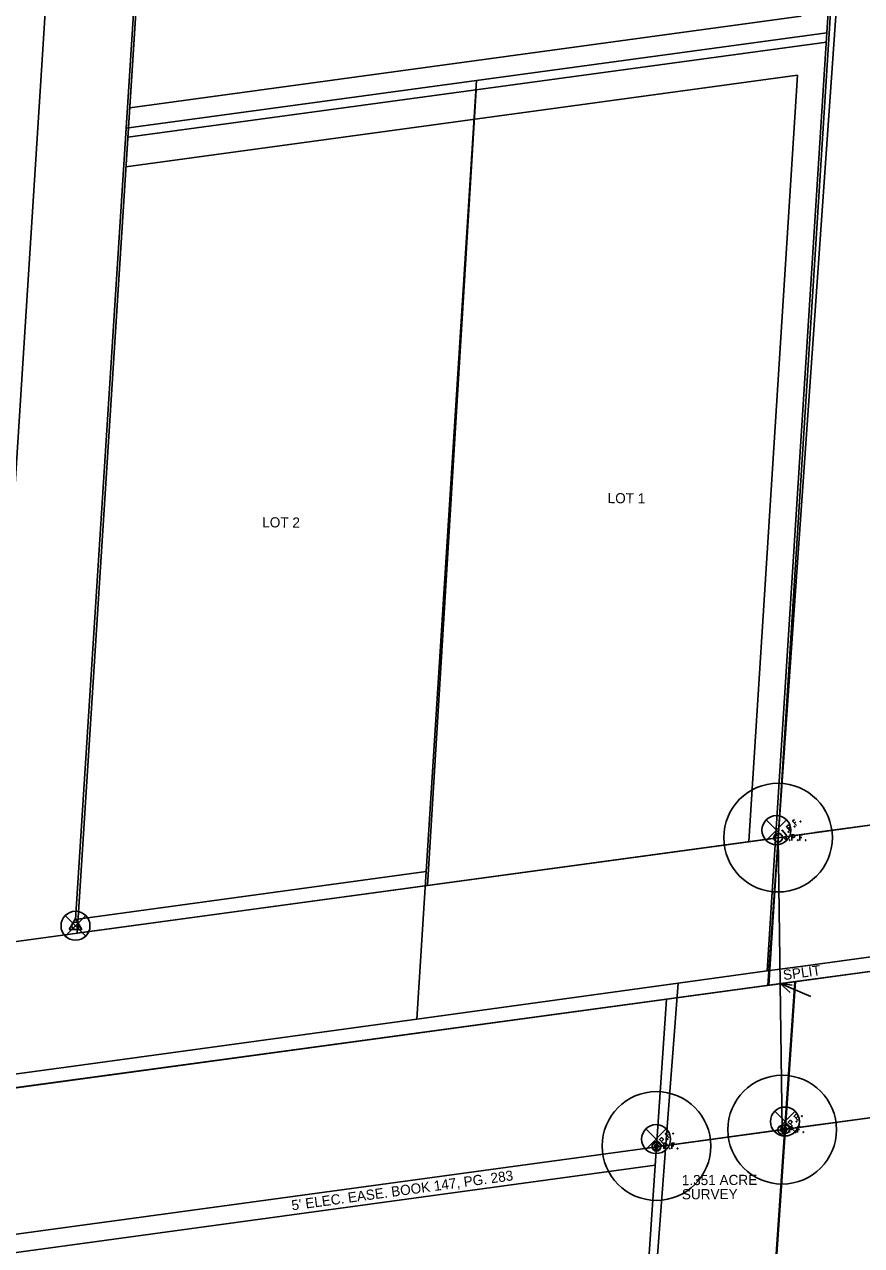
# Model space of a CAD drawing. Extents: x 1532954 to 1577849, y 698998 to 706606.
# Drawn here: x 1573832.2 to 1574063.3, y 703101.1 to 703438.2 of the extents above; entities that cross this region are included whole.
import ezdxf

# ---------------------------------------------------------------- set-up
doc = ezdxf.new("R2010")
doc.units = 0
for name, color, linetype in [('Default', 7, 'Continuous'), ('DV_X_Lot_Line', 7, 'Continuous'), ('DV_X_Property_Line', 7, 'Continuous'), ('RW_X_CL', 7, 'Continuous'), ('RW_X_Esmt_SH', 7, 'Continuous'), ('RW_X_Esmt_U', 7, 'Continuous'), ('RW_X_Fee_RW', 7, 'Continuous'), ('RW_X_Text', 7, 'Continuous'), ('SC_Scratch1', 7, 'Continuous'), ('SC_Scratch10', 7, 'Continuous'), ('SC_Scratch2', 7, 'Continuous'), ('SC_Scratch3', 7, 'Continuous'), ('SC_Scratch4', 7, 'Continuous'), ('SC_Scratch9', 7, 'Continuous'), ('SV_Control_Point', 7, 'Continuous'), ('SV_X_Mon_Cells_Found', 7, 'Continuous')]:
    doc.layers.add(name, color=color, linetype=linetype)

msp = doc.modelspace()

# ---------------------------------------------------------------- linework, layer by layer
at = {"layer": 'Default'}
for p, q in [((1574036.95, 703218.63), (1574042.61, 703212.98)), ((1574036.95, 703212.98), (1574042.61, 703218.63)), ((1574039.78, 703215.8), (1574039.78, 703215.8)), ((1573843.48, 703192.24), (1573849.14, 703186.58)), ((1573843.48, 703186.58), (1573849.14, 703192.24)), ((1573846.31, 703189.41), (1573846.31, 703189.41)), ((1574039.31, 703138.22), (1574044.97, 703132.56)), ((1574039.31, 703132.56), (1574044.97, 703138.22)), ((1574042.14, 703135.39), (1574042.14, 703135.39)), ((1574003.74, 703133.36), (1574009.4, 703127.7)), ((1574003.74, 703127.7), (1574009.4, 703133.36)), ((1574006.57, 703130.53), (1574006.57, 703130.53))]:
    msp.add_line(p, q, dxfattribs=at)
for centre in [(1574039.78, 703215.8), (1573846.31, 703189.41), (1574042.14, 703135.39), (1574006.57, 703130.53)]:
    msp.add_circle(centre, 4, dxfattribs=at)
at = {"layer": 'DV_X_Lot_Line'}
for p, q in [((1573943.52, 703200.54), (1573956.87, 703420.13)), ((1574044.83, 703173.97), (1574028.81, 702938.8))]:
    msp.add_line(p, q, dxfattribs=at)
at = {"layer": 'DV_X_Property_Line'}
for p, q in [((1574037.66, 703173), (1574084.63, 703911.12)), ((1573860.76, 703407.03), (1574053.61, 703433.31)), ((1573991.25, 702903.04), (1574009.46, 703169.15))]:
    msp.add_line(p, q, dxfattribs=at)
at = {"layer": 'RW_X_CL'}
msp.add_line((1573818.91, 703143.18), (1573849.35, 703621.38), dxfattribs=at)
at = {"layer": 'RW_X_Esmt_SH'}
for p, q in [((1574050.43, 703215.11), (1574859.76, 703325.41)), ((1571959, 702849.32), (1574870.56, 703246.15))]:
    msp.add_line(p, q, dxfattribs=at)
at = {"layer": 'RW_X_Esmt_U'}
for p, q in [((1573861.27, 703415.17), (1574046.66, 703440.44)), ((1573860.24, 703398.88), (1574045.63, 703424.15)), ((1574032.16, 703212.62), (1574045.63, 703424.15)), ((1574006.32, 703123.31), (1574006.67, 703128.4)), ((1573740.72, 703087.11), (1574006.32, 703123.31))]:
    msp.add_line(p, q, dxfattribs=at)
at = {"layer": 'RW_X_Fee_RW'}
for p, q in [((1573846.78, 703187.35), (1573874.62, 703624.83)), ((1573846.78, 703187.35), (1574040.25, 703213.72)), ((1574037.66, 703173), (1574040.25, 703213.72))]:
    msp.add_line(p, q, dxfattribs=at)
at = {"layer": 'SC_Scratch1'}
for points in [[(1574623.21, 704615.75), (1574580.13, 703940.99), (1574479.08, 703927.65), (1574283.38, 703901.81), (1574176.78, 703887.73), (1574134.84, 703230.69), (1574132.24, 703189.96), (1574047.81, 703178.38), (1574037.25, 703176.93), (1574039.84, 703217.66), (1574053.75, 703435.89), (1574059.56, 703527.11), (1574066.62, 703637.88), (1574073.68, 703748.66), (1574080.74, 703859.43), (1574081.75, 703875.18), (1574087.8, 703970.21), (1574094.86, 704080.98), (1574101.92, 704191.76)], [(1573381.77, 703087.06), (1573407.03, 703090.53), (1573503.76, 703103.79), (1573600.48, 703117.05), (1573696.98, 703130.28), (1573793.21, 703143.47), (1573818.48, 703146.94), (1573843.76, 703150.4), (1573940.5, 703163.67), (1574012.63, 703173.56), (1574009.55, 703132.76), (1573992.57, 702907.55), (1573992.57, 702907.55), (1574153.57, 702895.41), (1574152.55, 702881.84), (1574277.72, 702872.4), (1574506.31, 702855.16), (1574480.3, 702510.33), (1574373.41, 701092.97)]]:
    msp.add_lwpolyline(points, dxfattribs=at)
for points in [[(1574059.56, 703527.11), (1574059.56, 703527.11), (1574053.75, 703435.89), (1573957.01, 703422.72), (1573860.27, 703409.54), (1573868.54, 703539.28)], [(1574039.84, 703217.66), (1574037.25, 703176.93), (1574012.63, 703173.56), (1573940.5, 703163.67), (1573943.1, 703204.4), (1573957.01, 703422.72), (1574053.75, 703435.89)], [(1573943.1, 703204.4), (1573846.35, 703191.13), (1573860.27, 703409.54), (1573957.01, 703422.72)], [(1574173.16, 703155.19), (1574157.49, 702947.32), (1574153.57, 702895.41), (1573992.57, 702907.55), (1573992.57, 702907.55), (1574009.55, 703132.76), (1574012.63, 703173.56), (1574037.25, 703176.93), (1574047.81, 703178.38), (1574132.24, 703189.96), (1574176.24, 703195.99)]]:
    msp.add_lwpolyline(points, close=True, dxfattribs=at)
at = {"layer": 'SC_Scratch10'}
for p, q in [((1571190.11, 702825.26), (1574958.12, 703338.82)), ((1571190.11, 702825.26), (1574958.12, 703338.82)), ((1571190.11, 702825.26), (1574958.12, 703338.82)), ((1571195.51, 702785.63), (1574963.52, 703299.19)), ((1571200.91, 702745.99), (1574968.92, 703259.55))]:
    msp.add_line(p, q, dxfattribs=at)
at = {"layer": 'SC_Scratch2'}
for p, q in [((1574175.23, 705334.64), (1574037.66, 703173)), ((1573874.62, 703624.83), (1573846.78, 703187.35)), ((1573849.35, 703621.38), (1573818.91, 703143.18)), ((1574046.66, 703440.44), (1573861.27, 703415.17)), ((1574053.61, 703433.31), (1573860.76, 703407.03)), ((1574045.63, 703424.15), (1573860.24, 703398.88)), ((1574045.63, 703424.15), (1574032.16, 703212.62)), ((1573943.52, 703200.54), (1573956.87, 703420.13)), ((1574040.25, 703213.72), (1573846.78, 703187.35)), ((1574037.66, 703173), (1573356.99, 703080.23))]:
    msp.add_line(p, q, dxfattribs=at)
at = {"layer": 'SC_Scratch3'}
for p, q in [((1574037.38, 703172.96), (1574089.44, 703911.99)), ((1574832.97, 703321.42), (1574040.25, 703213.72)), ((1574830.1, 703280.66), (1574037.38, 703172.96)), ((1574533, 703240.3), (1572963.42, 703027.05)), ((1574172.81, 703191.36), (1574045.04, 703174)), ((1574045.04, 703174), (1574009.47, 703169.17)), ((1574045.04, 703174), (1574028.74, 702936.66)), ((1574009.47, 703169.17), (1573991.19, 702903.04)), ((1574042.24, 703133.25), (1574006.67, 703128.42))]:
    msp.add_line(p, q, dxfattribs=at)
for points in [[(1574044.81, 703218.78), (1574044.24, 703218.28), (1574045.29, 703217.07)], [(1574044.75, 703217.69), (1574045.16, 703218.05)], [(1574046.31, 703218.25), (1574046.35, 703218.29), (1574046.4, 703218.29), (1574046.45, 703218.28), (1574046.5, 703218.23), (1574046.5, 703218.17), (1574046.5, 703218.13), (1574046.45, 703218.09), (1574046.41, 703218.09), (1574046.36, 703218.1), (1574046.31, 703218.15), (1574046.31, 703218.21), (1574046.31, 703218.25)], [(1574041.24, 703215.65), (1574041.5, 703215.88)], [(1574042.43, 703214.56), (1574041.37, 703215.76)], [(1574042.29, 703214.44), (1574042.56, 703214.68)], [(1574043.6, 703215.59), (1574042.55, 703216.8), (1574042.95, 703217.14), (1574043, 703217.17), (1574043.07, 703217.2), (1574043.11, 703217.21), (1574043.15, 703217.21), (1574043.23, 703217.19), (1574043.29, 703217.16), (1574043.38, 703217.1), (1574043.48, 703216.99), (1574043.5, 703216.94), (1574043.54, 703216.87), (1574043.56, 703216.78), (1574043.55, 703216.72), (1574043.54, 703216.68), (1574043.52, 703216.62), (1574043.46, 703216.56), (1574043.06, 703216.21)], [(1574043.01, 703215.35), (1574043.05, 703215.39), (1574043.09, 703215.39), (1574043.15, 703215.38), (1574043.19, 703215.33), (1574043.2, 703215.27), (1574043.19, 703215.23), (1574043.15, 703215.19), (1574043.11, 703215.19), (1574043.05, 703215.21), (1574043.01, 703215.25), (1574043, 703215.31), (1574043.01, 703215.35)], [(1574044.7, 703216.84), (1574044.74, 703216.87), (1574044.78, 703216.88), (1574044.84, 703216.86), (1574044.88, 703216.81), (1574044.89, 703216.75), (1574044.88, 703216.71), (1574044.84, 703216.67), (1574044.8, 703216.67), (1574044.74, 703216.69), (1574044.7, 703216.74), (1574044.69, 703216.8), (1574044.7, 703216.84)], [(1574008.64, 703129.27), (1574007.51, 703130.4), (1574007.88, 703130.78), (1574007.93, 703130.81), (1574008, 703130.84), (1574008.04, 703130.85), (1574008.08, 703130.86), (1574008.16, 703130.84), (1574008.23, 703130.82), (1574008.31, 703130.77), (1574008.42, 703130.66), (1574008.45, 703130.62), (1574008.49, 703130.55), (1574008.52, 703130.45), (1574008.51, 703130.4), (1574008.51, 703130.36), (1574008.49, 703130.3), (1574008.43, 703130.23), (1574008.06, 703129.85)], [(1574009.63, 703132.54), (1574009.09, 703132), (1574010.23, 703130.87)], [(1574009.65, 703130.59), (1574009.69, 703130.63), (1574009.73, 703130.64), (1574009.79, 703130.62), (1574009.83, 703130.58), (1574009.84, 703130.52), (1574009.84, 703130.48), (1574009.8, 703130.44), (1574009.76, 703130.44), (1574009.7, 703130.45), (1574009.66, 703130.49), (1574009.64, 703130.55), (1574009.65, 703130.59)], [(1574009.65, 703131.45), (1574010.03, 703131.83)], [(1574011.16, 703132.12), (1574011.2, 703132.16), (1574011.24, 703132.16), (1574011.3, 703132.15), (1574011.35, 703132.11), (1574011.36, 703132.05), (1574011.35, 703132.01), (1574011.31, 703131.97), (1574011.27, 703131.96), (1574011.21, 703131.97), (1574011.17, 703132.02), (1574011.16, 703132.08), (1574011.16, 703132.12)]]:
    msp.add_lwpolyline(points, dxfattribs=at)
for centre, radius in [((1574040.25, 703213.72), 1.2), ((1574006.67, 703128.42), 1.2), ((1574006.67, 703128.42), 0.495)]:
    msp.add_circle(centre, radius, dxfattribs=at)
at = {"layer": 'SC_Scratch4'}
for p, q in [((1574045.04, 703174.01), (1574172.81, 703191.37)), ((1574028.74, 702936.67), (1574045.04, 703174.01)), ((1574042.24, 703133.26), (1574170.01, 703150.62))]:
    msp.add_line(p, q, dxfattribs=at)
for points in [[(1574045.2, 703137.38), (1574044.66, 703136.84), (1574045.8, 703135.71)], [(1574046.73, 703136.96), (1574046.77, 703137), (1574046.81, 703137), (1574046.87, 703136.99), (1574046.92, 703136.94), (1574046.93, 703136.89), (1574046.92, 703136.84), (1574046.89, 703136.81), (1574046.84, 703136.8), (1574046.79, 703136.81), (1574046.74, 703136.86), (1574046.73, 703136.92), (1574046.73, 703136.96)], [(1574044.22, 703134.11), (1574043.08, 703135.24), (1574043.45, 703135.62), (1574043.5, 703135.65), (1574043.57, 703135.68), (1574043.61, 703135.69), (1574043.65, 703135.69), (1574043.73, 703135.68), (1574043.8, 703135.66), (1574043.89, 703135.61), (1574043.99, 703135.5), (1574044.02, 703135.46), (1574044.06, 703135.39), (1574044.09, 703135.29), (1574044.09, 703135.24), (1574044.08, 703135.19), (1574044.06, 703135.14), (1574044.01, 703135.07), (1574043.63, 703134.69)], [(1574045.22, 703135.43), (1574045.26, 703135.47), (1574045.3, 703135.48), (1574045.36, 703135.46), (1574045.4, 703135.42), (1574045.42, 703135.36), (1574045.41, 703135.32), (1574045.37, 703135.28), (1574045.33, 703135.27), (1574045.27, 703135.29), (1574045.23, 703135.33), (1574045.21, 703135.39), (1574045.22, 703135.43)], [(1574045.22, 703136.29), (1574045.6, 703136.67)]]:
    msp.add_lwpolyline(points, dxfattribs=at)
for radius in [1.2, 0.495]:
    msp.add_circle((1574042.24, 703133.26), radius, dxfattribs=at)
at = {"layer": 'SC_Scratch9'}
for p, q in [((1574040.25, 703213.73), (1574041.39, 703133.13)), ((1574040.82, 703173.43), (1574049.3, 703169.89)), ((1574040.82, 703173.43), (1574043.61, 703171.02)), ((1574040.82, 703173.43), (1574044.14, 703173.01))]:
    msp.add_line(p, q, dxfattribs=at)
for centre in [(1574040.25, 703213.73), (1574041.39, 703133.13), (1574006.68, 703128.63)]:
    msp.add_circle(centre, 15, dxfattribs=at)
at = {"layer": 'SV_Control_Point'}
msp.add_line((1573846.31, 703189.41), (1573846.31, 703189.41), dxfattribs=at)
msp.add_lwpolyline([(1573844.57, 703188.41), (1573846.31, 703191.41), (1573848.04, 703188.41)], close=True, dxfattribs=at)
msp.add_circle((1573846.31, 703189.41), 1, dxfattribs=at)
at = {"layer": 'SV_X_Mon_Cells_Found'}
msp.add_line((1574040.25, 703213.85), (1574040.25, 703212.96), dxfattribs=at)
for points in [[(1574042.28, 703214.53), (1574042.63, 703214.53)], [(1574042.46, 703212.93), (1574042.46, 703214.53)], [(1574044.02, 703212.93), (1574044.02, 703214.53), (1574044.55, 703214.53), (1574044.61, 703214.52), (1574044.68, 703214.49), (1574044.72, 703214.47), (1574044.75, 703214.44), (1574044.79, 703214.38), (1574044.83, 703214.31), (1574044.85, 703214.21), (1574044.85, 703214.06), (1574044.84, 703214.01), (1574044.82, 703213.94), (1574044.77, 703213.85), (1574044.73, 703213.81), (1574044.7, 703213.79), (1574044.64, 703213.76), (1574044.55, 703213.75), (1574044.02, 703213.75)], [(1574047.03, 703214.53), (1574046.27, 703214.53), (1574046.27, 703212.93)], [(1574042.28, 703212.93), (1574042.63, 703212.93)], [(1574043.42, 703213.14), (1574043.47, 703213.14), (1574043.51, 703213.12), (1574043.54, 703213.07), (1574043.54, 703213), (1574043.51, 703212.95), (1574043.47, 703212.93), (1574043.42, 703212.93), (1574043.38, 703212.95), (1574043.35, 703213), (1574043.35, 703213.07), (1574043.38, 703213.12), (1574043.42, 703213.14)], [(1574045.67, 703213.14), (1574045.72, 703213.14), (1574045.75, 703213.12), (1574045.79, 703213.07), (1574045.79, 703213), (1574045.75, 703212.95), (1574045.72, 703212.93), (1574045.67, 703212.93), (1574045.63, 703212.95), (1574045.6, 703213), (1574045.6, 703213.07), (1574045.63, 703213.12), (1574045.67, 703213.14)], [(1574046.27, 703213.75), (1574046.81, 703213.75)], [(1574047.82, 703213.14), (1574047.87, 703213.14), (1574047.9, 703213.12), (1574047.94, 703213.07), (1574047.94, 703213), (1574047.9, 703212.95), (1574047.87, 703212.93), (1574047.82, 703212.93), (1574047.78, 703212.95), (1574047.75, 703213), (1574047.75, 703213.07), (1574047.78, 703213.12), (1574047.82, 703213.14)], [(1574043.38, 703132.33), (1574043.38, 703133.93), (1574043.91, 703133.93), (1574043.97, 703133.91), (1574044.05, 703133.89), (1574044.08, 703133.86), (1574044.11, 703133.84), (1574044.16, 703133.77), (1574044.19, 703133.71), (1574044.21, 703133.61), (1574044.21, 703133.46), (1574044.2, 703133.41), (1574044.18, 703133.33), (1574044.13, 703133.25), (1574044.09, 703133.21), (1574044.06, 703133.18), (1574044, 703133.16), (1574043.91, 703133.14), (1574043.38, 703133.14)], [(1574046.39, 703133.93), (1574045.63, 703133.93), (1574045.63, 703132.33)], [(1574045.03, 703132.54), (1574045.08, 703132.54), (1574045.12, 703132.51), (1574045.15, 703132.46), (1574045.15, 703132.4), (1574045.12, 703132.35), (1574045.08, 703132.33), (1574045.03, 703132.33), (1574044.99, 703132.35), (1574044.96, 703132.4), (1574044.96, 703132.46), (1574044.99, 703132.51), (1574045.03, 703132.54)], [(1574045.63, 703133.14), (1574046.17, 703133.14)], [(1574047.18, 703132.54), (1574047.23, 703132.54), (1574047.26, 703132.51), (1574047.3, 703132.46), (1574047.3, 703132.4), (1574047.26, 703132.35), (1574047.23, 703132.33), (1574047.18, 703132.33), (1574047.14, 703132.35), (1574047.11, 703132.4), (1574047.11, 703132.46), (1574047.14, 703132.51), (1574047.18, 703132.54)], [(1574008.68, 703127.83), (1574008.68, 703129.43), (1574009.21, 703129.43), (1574009.27, 703129.42), (1574009.34, 703129.39), (1574009.38, 703129.37), (1574009.41, 703129.34), (1574009.45, 703129.28), (1574009.49, 703129.21), (1574009.51, 703129.11), (1574009.51, 703128.96), (1574009.5, 703128.91), (1574009.47, 703128.84), (1574009.43, 703128.75), (1574009.39, 703128.71), (1574009.35, 703128.69), (1574009.3, 703128.66), (1574009.21, 703128.65), (1574008.68, 703128.65)], [(1574010.32, 703128.04), (1574010.38, 703128.04), (1574010.41, 703128.02), (1574010.44, 703127.97), (1574010.44, 703127.9), (1574010.41, 703127.85), (1574010.38, 703127.83), (1574010.32, 703127.83), (1574010.29, 703127.85), (1574010.26, 703127.9), (1574010.26, 703127.97), (1574010.29, 703128.02), (1574010.32, 703128.04)], [(1574011.69, 703129.43), (1574010.93, 703129.43), (1574010.93, 703127.83)], [(1574010.93, 703128.65), (1574011.47, 703128.65)], [(1574012.47, 703128.04), (1574012.53, 703128.04), (1574012.56, 703128.02), (1574012.59, 703127.97), (1574012.59, 703127.9), (1574012.56, 703127.85), (1574012.53, 703127.83), (1574012.47, 703127.83), (1574012.44, 703127.85), (1574012.41, 703127.9), (1574012.41, 703127.97), (1574012.44, 703128.02), (1574012.47, 703128.04)]]:
    msp.add_lwpolyline(points, dxfattribs=at)
for centre, radius in [((1574040.25, 703213.73), 1.2), ((1574040.25, 703214.38), 0.16), ((1574041.39, 703133.13), 1.2), ((1574041.39, 703133.13), 0.495), ((1574006.68, 703128.63), 1.2), ((1574006.68, 703128.63), 0.495)]:
    msp.add_circle(centre, radius, dxfattribs=at)

# ---------------------------------------------------------------- texts
at = {"layer": 'RW_X_Text'}
msp.add_text("5' ELEC. EASE. BOOK 147, PG. 283", height=2.8, rotation=7.7687, dxfattribs=at).set_placement((1573906.14, 703110.84))
at = {"layer": 'SC_Scratch2'}
for s, p in [('LOT 1', (1573993.19, 703306.05)), ('LOT 2', (1573897.85, 703299.38))]:
    msp.add_text(s, height=2.8, rotation=359.4613, dxfattribs=at).set_placement(p)
at = {"layer": 'SC_Scratch3'}
for s, p in [('1.351 ACRE', (1574013.68, 703117.81)), ('SURVEY', (1574013.7, 703113.91))]:
    msp.add_text(s, height=2.8, rotation=0.2372, dxfattribs=at).set_placement(p)
at = {"layer": 'SC_Scratch9'}
msp.add_text('SPLIT', height=2.8, rotation=7.7687, dxfattribs=at).set_placement((1574041.82, 703174.4))

doc.saveas('drawing.dxf')
